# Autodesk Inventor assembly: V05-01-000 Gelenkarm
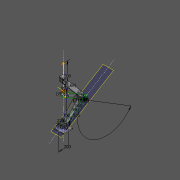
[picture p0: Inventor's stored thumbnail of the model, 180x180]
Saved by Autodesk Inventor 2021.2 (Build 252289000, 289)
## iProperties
RuleStatus: InUse
Company: R-Kon - Rodermund Konstruktion und Entwicklung GmbH
BeforeDocSave0: Parameter übertragen
AfterAnyParamChange0: Parameter übertragen
Created: 2020-09
Part Number: V05-01-000 Gelenkarm
Material: Generisch
Description: Baugruppe
Document SubType Name: Assembly
Designer: Felix Rodermund
Engineer: Felix Rodermund
Mass: 57732.2 g
Surface Area: 5681.46 cm^2
Volume: 7354.42 cm^3
Density: 7.85 g/cm^3
EinheitenloseMasse: 0.0
StatusCheck: 1
Title: Baugruppe
Author: Felix Rodermund
Revision Number: 0
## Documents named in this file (5)
- C:\Users\Felix\Arbeit lokal\Content Marketing\CAD Video\Video5\V05-01-000 Gelenkarm.iam
- C:\Users\Felix\Arbeit lokal\Content Marketing\CAD Video\Video5\V05-01-001 Armsegment.ipt
- C:\Users\Felix\Arbeit lokal\Content Marketing\CAD Video\Video5\V05-01-002 Befestigungslager.ipt
- C:\Users\Felix\Arbeit lokal\Content Marketing\CAD Video\Video5\V05-01-000 Gelenkarm Skelett.ipt
- C:\Users\Felix\Arbeit lokal\Content Marketing\CAD Video\Video5\V05-01-003 Konsole.ipt
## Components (5 placed, 4 different names)
1. V04-01-000 Gelenkarm Skelett:1 — Hub max, Hub min, Hubgrenzen
2. V04-01-001 Armsegment:3 — Passend:1, Passend:4, Fluchtend:4
3. V04-01-002 Befestigungslager:1 — Passend:4
4. V04-01-001 Armsegment:2 — Passend:1, Fluchtend:3, Passend:5, Passend:7
5. V04-01-003 Konsole:1 — Fluchtend:5, Fluchtend:6, Hub max, Hub min, Hubgrenzen, Passend:7
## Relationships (11: Flush 6, Mate 5)
- Hub max [Mate]: V04-01-000 Gelenkarm Skelett:1 ↔ V04-01-003 Konsole:1
- Hub min [Flush]: V04-01-000 Gelenkarm Skelett:1 ↔ V04-01-003 Konsole:1
- Hubgrenzen [Flush]: V04-01-000 Gelenkarm Skelett:1 ↔ V04-01-003 Konsole:1
- Fluchtend:3 [Flush]: V04-01-001 Armsegment:2
- Passend:1 [Mate]: V04-01-001 Armsegment:3 ↔ V04-01-001 Armsegment:2
- Passend:4 [Mate]: V04-01-001 Armsegment:3 ↔ V04-01-002 Befestigungslager:1
- Fluchtend:4 [Flush]: V04-01-001 Armsegment:3
- Passend:5 [Mate]: V04-01-001 Armsegment:2
- Fluchtend:5 [Flush]: V04-01-003 Konsole:1
- Fluchtend:6 [Flush]: V04-01-003 Konsole:1
- Passend:7 [Mate]: V04-01-001 Armsegment:2 ↔ V04-01-003 Konsole:1
